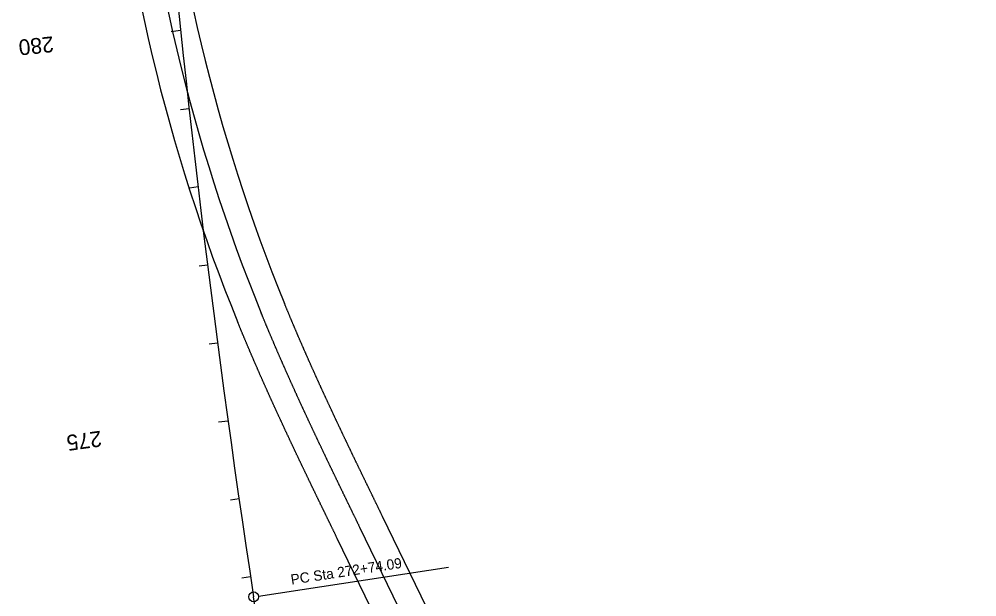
# Model space of a CAD drawing. Extents: x 5180909 to 5237144, y 3695282 to 3720102.
# Drawn here: x 5196668 to 5197885, y 3710731 to 3711465 of the extents above; entities that cross this region are included whole.
import ezdxf

# ---------------------------------------------------------------- set-up
doc = ezdxf.new("R2010")
doc.units = 0
for name, color, linetype in [('Alignment', 7, 'Continuous'), ('brgPreStructureNew', 7, 'Continuous'), ('Default', 7, 'Continuous'), ('DisFieldPoint', 7, 'Continuous'), ('dsnEntrancePaved', 7, 'Continuous'), ('dsnSidewalkShadingRamp', 7, 'Continuous')]:
    doc.layers.add(name, color=color, linetype=linetype)

msp = doc.modelspace()

# ---------------------------------------------------------------- linework, layer by layer
at = {"layer": 'Alignment'}
msp.add_arc((5212287.9, 3713070.6), 15500, 180.86138, 188.68311, dxfattribs=at)
at = {"layer": 'brgPreStructureNew'}
msp.add_open_spline([(5197100.6, 3710818.9), (5197100, 3710820.1), (5197099.4, 3710821.3), (5197098.8, 3710822.6), (5197098.2, 3710823.8), (5197097.6, 3710825), (5197097.1, 3710826.2), (5197096.5, 3710827.4), (5197095.9, 3710828.6), (5197095.3, 3710829.8), (5197094.7, 3710831.1), (5197094.1, 3710832.3), (5197093.5, 3710833.5), (5197092.9, 3710834.7), (5197092.3, 3710835.9), (5197091.7, 3710837.1), (5197091.1, 3710838.4), (5197090.6, 3710839.6), (5197090, 3710840.8), (5197089.4, 3710842), (5197088.8, 3710843.2), (5197088.2, 3710844.4), (5197087.6, 3710845.6), (5197087, 3710846.9), (5197086.4, 3710848.1), (5197085.8, 3710849.3), (5197085.2, 3710850.5), (5197084.6, 3710851.7), (5197084.1, 3710852.9), (5197083.5, 3710854.2), (5197082.9, 3710855.4), (5197082.3, 3710856.6), (5197081.7, 3710857.8), (5197081.1, 3710859), (5197080.5, 3710860.2), (5197079.9, 3710861.5), (5197079.3, 3710862.7), (5197078.8, 3710863.9), (5197078.2, 3710865.1), (5197077.6, 3710866.3), (5197077, 3710867.5), (5197076.4, 3710868.7), (5197075.8, 3710870), (5197075.2, 3710871.2), (5197074.6, 3710872.4), (5197074, 3710873.6), (5197073.5, 3710874.8), (5197072.9, 3710876), (5197072.3, 3710877.3), (5197071.7, 3710878.5), (5197071.1, 3710879.7), (5197070.5, 3710880.9), (5197069.9, 3710882.1), (5197069.3, 3710883.4), (5197068.8, 3710884.6), (5197068.2, 3710885.8), (5197067.6, 3710887), (5197067, 3710888.2), (5197066.4, 3710889.4), (5197065.8, 3710890.7), (5197065.2, 3710891.9), (5197064.7, 3710893.1), (5197064.1, 3710894.3), (5197063.5, 3710895.5), (5197062.9, 3710896.7), (5197062.3, 3710898), (5197061.7, 3710899.2), (5197061.1, 3710900.4), (5197060.6, 3710901.6), (5197060, 3710902.8), (5197059.4, 3710904.1), (5197058.8, 3710905.3), (5197058.2, 3710906.5), (5197057.6, 3710907.7), (5197057.1, 3710908.9), (5197056.5, 3710910.2), (5197055.9, 3710911.4), (5197055.3, 3710912.6), (5197054.7, 3710913.8), (5197054.2, 3710915), (5197053.6, 3710916.3), (5197053, 3710917.5), (5197052.4, 3710918.7), (5197051.8, 3710919.9), (5197051.3, 3710921.1), (5197050.7, 3710922.4), (5197050.1, 3710923.6), (5197049.5, 3710924.8), (5197048.9, 3710926), (5197048.4, 3710927.2), (5197047.8, 3710928.5), (5197047.2, 3710929.7), (5197046.6, 3710930.9), (5197046, 3710932.1), (5197045.5, 3710933.3), (5197044.9, 3710934.6), (5197044.3, 3710935.8), (5197043.7, 3710937), (5197043.2, 3710938.2), (5197042.6, 3710939.5), (5197042, 3710940.7), (5197041.4, 3710941.9), (5197040.9, 3710943.1), (5197040.3, 3710944.4), (5197039.7, 3710945.6), (5197039.1, 3710946.8), (5197038.6, 3710948), (5197038, 3710949.2), (5197037.4, 3710950.5), (5197036.8, 3710951.7), (5197036.3, 3710952.9), (5197035.7, 3710954.1), (5197035.1, 3710955.4), (5197034.6, 3710956.6), (5197034, 3710957.8), (5197033.4, 3710959), (5197032.9, 3710960.3), (5197032.3, 3710961.5), (5197031.7, 3710962.7), (5197031.1, 3710963.9), (5197030.6, 3710965.2), (5197030, 3710966.4), (5197029.4, 3710967.6), (5197028.9, 3710968.9), (5197028.3, 3710970.1), (5197027.7, 3710971.3), (5197027.2, 3710972.5), (5197026.6, 3710973.8), (5197026, 3710975), (5197025.5, 3710976.2), (5197024.9, 3710977.4), (5197024.4, 3710978.7), (5197023.8, 3710979.9), (5197023.2, 3710981.1), (5197022.7, 3710982.4), (5197022.1, 3710983.6), (5197021.5, 3710984.8), (5197021, 3710986), (5197020.4, 3710987.3), (5197019.9, 3710988.5), (5197019.3, 3710989.7), (5197018.7, 3710991), (5197018.2, 3710992.2), (5197017.6, 3710993.4), (5197017.1, 3710994.7), (5197016.5, 3710995.9), (5197016, 3710997.1), (5197015.4, 3710998.4), (5197014.8, 3710999.6), (5197014.3, 3711000.8), (5197013.7, 3711002), (5197013.2, 3711003.3), (5197012.6, 3711004.5), (5197012.1, 3711005.7), (5197011.5, 3711007), (5197011, 3711008.2), (5197010.4, 3711009.4), (5197009.9, 3711010.7), (5197009.3, 3711011.9), (5197008.8, 3711013.1), (5197008.2, 3711014.4), (5197007.7, 3711015.6), (5197007.1, 3711016.8), (5197006.6, 3711018.1), (5197006, 3711019.3), (5197005.5, 3711020.6), (5197004.9, 3711021.8), (5197004.4, 3711023), (5197003.8, 3711024.3), (5197003.3, 3711025.5), (5197002.7, 3711026.7), (5197002.2, 3711028), (5197001.7, 3711029.2), (5197001.1, 3711030.4), (5197000.6, 3711031.7), (5197000, 3711032.9), (5196999.5, 3711034.2), (5196998.9, 3711035.4), (5196998.4, 3711036.6), (5196997.9, 3711037.9), (5196997.3, 3711039.1), (5196996.8, 3711040.4), (5196996.2, 3711041.6), (5196995.7, 3711042.8), (5196995.2, 3711044.1), (5196994.6, 3711045.3), (5196994.1, 3711046.6), (5196993.6, 3711047.8), (5196993, 3711049), (5196992.5, 3711050.3), (5196992, 3711051.5), (5196991.4, 3711052.8), (5196990.9, 3711054), (5196990.4, 3711055.3), (5196989.8, 3711056.5), (5196989.3, 3711057.7), (5196988.8, 3711059), (5196988.3, 3711060.2), (5196987.7, 3711061.5), (5196987.2, 3711062.7), (5196986.7, 3711064), (5196986.2, 3711065.2), (5196985.6, 3711066.4), (5196985.1, 3711067.7), (5196984.6, 3711068.9), (5196984.1, 3711070.2), (5196983.5, 3711071.4), (5196983, 3711072.7), (5196982.5, 3711073.9), (5196982, 3711075.2), (5196981.5, 3711076.4), (5196980.9, 3711077.7), (5196980.4, 3711078.9), (5196979.9, 3711080.2), (5196979.4, 3711081.4), (5196978.9, 3711082.7), (5196978.3, 3711083.9), (5196977.8, 3711085.2), (5196977.3, 3711086.4), (5196976.8, 3711087.7), (5196976.3, 3711088.9), (5196975.8, 3711090.2), (5196975.3, 3711091.4)], degree=3, dxfattribs=at)
msp.add_open_spline([(5197100.6, 3710818.9), (5197100, 3710820.1), (5197099.4, 3710821.3), (5197098.8, 3710822.6), (5197098.2, 3710823.8), (5197097.6, 3710825), (5197097.1, 3710826.2), (5197096.5, 3710827.4), (5197095.9, 3710828.6), (5197095.3, 3710829.8), (5197094.7, 3710831.1), (5197094.1, 3710832.3), (5197093.5, 3710833.5), (5197092.9, 3710834.7), (5197092.3, 3710835.9), (5197091.7, 3710837.1), (5197091.1, 3710838.4), (5197090.6, 3710839.6), (5197090, 3710840.8), (5197089.4, 3710842), (5197088.8, 3710843.2), (5197088.2, 3710844.4), (5197087.6, 3710845.6), (5197087, 3710846.9), (5197086.4, 3710848.1), (5197085.8, 3710849.3), (5197085.2, 3710850.5), (5197084.6, 3710851.7), (5197084.1, 3710852.9), (5197083.5, 3710854.2), (5197082.9, 3710855.4), (5197082.3, 3710856.6), (5197081.7, 3710857.8), (5197081.1, 3710859), (5197080.5, 3710860.2), (5197079.9, 3710861.5), (5197079.3, 3710862.7), (5197078.8, 3710863.9), (5197078.2, 3710865.1), (5197077.6, 3710866.3), (5197077, 3710867.5), (5197076.4, 3710868.7), (5197075.8, 3710870), (5197075.2, 3710871.2), (5197074.6, 3710872.4), (5197074, 3710873.6), (5197073.5, 3710874.8), (5197072.9, 3710876), (5197072.3, 3710877.3), (5197071.7, 3710878.5), (5197071.1, 3710879.7), (5197070.5, 3710880.9), (5197069.9, 3710882.1), (5197069.3, 3710883.4), (5197068.8, 3710884.6), (5197068.2, 3710885.8), (5197067.6, 3710887), (5197067, 3710888.2), (5197066.4, 3710889.4), (5197065.8, 3710890.7), (5197065.2, 3710891.9), (5197064.7, 3710893.1), (5197064.1, 3710894.3), (5197063.5, 3710895.5), (5197062.9, 3710896.7), (5197062.3, 3710898), (5197061.7, 3710899.2), (5197061.1, 3710900.4), (5197060.6, 3710901.6), (5197060, 3710902.8), (5197059.4, 3710904.1), (5197058.8, 3710905.3), (5197058.2, 3710906.5), (5197057.6, 3710907.7), (5197057.1, 3710908.9), (5197056.5, 3710910.2), (5197055.9, 3710911.4), (5197055.3, 3710912.6), (5197054.7, 3710913.8), (5197054.2, 3710915), (5197053.6, 3710916.3), (5197053, 3710917.5), (5197052.4, 3710918.7), (5197051.8, 3710919.9), (5197051.3, 3710921.1), (5197050.7, 3710922.4), (5197050.1, 3710923.6), (5197049.5, 3710924.8), (5197048.9, 3710926), (5197048.4, 3710927.2), (5197047.8, 3710928.5), (5197047.2, 3710929.7), (5197046.6, 3710930.9), (5197046, 3710932.1), (5197045.5, 3710933.3), (5197044.9, 3710934.6), (5197044.3, 3710935.8), (5197043.7, 3710937), (5197043.2, 3710938.2), (5197042.6, 3710939.5), (5197042, 3710940.7), (5197041.4, 3710941.9), (5197040.9, 3710943.1), (5197040.3, 3710944.4), (5197039.7, 3710945.6), (5197039.1, 3710946.8), (5197038.6, 3710948), (5197038, 3710949.2), (5197037.4, 3710950.5), (5197036.8, 3710951.7), (5197036.3, 3710952.9), (5197035.7, 3710954.1), (5197035.1, 3710955.4), (5197034.6, 3710956.6), (5197034, 3710957.8), (5197033.4, 3710959), (5197032.9, 3710960.3), (5197032.3, 3710961.5), (5197031.7, 3710962.7), (5197031.1, 3710963.9), (5197030.6, 3710965.2), (5197030, 3710966.4), (5197029.4, 3710967.6), (5197028.9, 3710968.9), (5197028.3, 3710970.1), (5197027.7, 3710971.3), (5197027.2, 3710972.5), (5197026.6, 3710973.8), (5197026, 3710975), (5197025.5, 3710976.2), (5197024.9, 3710977.4), (5197024.4, 3710978.7), (5197023.8, 3710979.9), (5197023.2, 3710981.1), (5197022.7, 3710982.4), (5197022.1, 3710983.6), (5197021.5, 3710984.8), (5197021, 3710986), (5197020.4, 3710987.3), (5197019.9, 3710988.5), (5197019.3, 3710989.7), (5197018.7, 3710991), (5197018.2, 3710992.2), (5197017.6, 3710993.4), (5197017.1, 3710994.7), (5197016.5, 3710995.9), (5197016, 3710997.1), (5197015.4, 3710998.4), (5197014.8, 3710999.6), (5197014.3, 3711000.8), (5197013.7, 3711002), (5197013.2, 3711003.3), (5197012.6, 3711004.5), (5197012.1, 3711005.7), (5197011.5, 3711007), (5197011, 3711008.2), (5197010.4, 3711009.4), (5197009.9, 3711010.7), (5197009.3, 3711011.9), (5197008.8, 3711013.1), (5197008.2, 3711014.4), (5197007.7, 3711015.6), (5197007.1, 3711016.8), (5197006.6, 3711018.1), (5197006, 3711019.3), (5197005.5, 3711020.6), (5197004.9, 3711021.8), (5197004.4, 3711023), (5197003.8, 3711024.3), (5197003.3, 3711025.5), (5197002.7, 3711026.7), (5197002.2, 3711028), (5197001.7, 3711029.2), (5197001.1, 3711030.4), (5197000.6, 3711031.7), (5197000, 3711032.9), (5196999.5, 3711034.2), (5196998.9, 3711035.4), (5196998.4, 3711036.6), (5196997.9, 3711037.9), (5196997.3, 3711039.1), (5196996.8, 3711040.4), (5196996.2, 3711041.6), (5196995.7, 3711042.8), (5196995.2, 3711044.1), (5196994.6, 3711045.3), (5196994.1, 3711046.6), (5196993.6, 3711047.8), (5196993, 3711049), (5196992.5, 3711050.3), (5196992, 3711051.5), (5196991.4, 3711052.8), (5196990.9, 3711054), (5196990.4, 3711055.3), (5196989.8, 3711056.5), (5196989.3, 3711057.7), (5196988.8, 3711059), (5196988.3, 3711060.2), (5196987.7, 3711061.5), (5196987.2, 3711062.7), (5196986.7, 3711064), (5196986.2, 3711065.2), (5196985.6, 3711066.4), (5196985.1, 3711067.7), (5196984.6, 3711068.9), (5196984.1, 3711070.2), (5196983.5, 3711071.4), (5196983, 3711072.7), (5196982.5, 3711073.9), (5196982, 3711075.2), (5196981.5, 3711076.4), (5196980.9, 3711077.7), (5196980.4, 3711078.9), (5196979.9, 3711080.2), (5196979.4, 3711081.4), (5196978.9, 3711082.7), (5196978.3, 3711083.9), (5196977.8, 3711085.2), (5196977.3, 3711086.4), (5196976.8, 3711087.7), (5196976.3, 3711088.9), (5196975.8, 3711090.2), (5196975.3, 3711091.4)], degree=3, dxfattribs=at)
at = {"layer": 'Default'}
msp.add_line((5197884.8, 3704711.8), (5196965.6, 3710730.6), dxfattribs=at)
msp.add_arc((5212287.9, 3713070.6), 15500, 180.86138, 188.68311, dxfattribs=at)
at = {"layer": 'DisFieldPoint'}
for p, q in [((5196945.7, 3711079.3), (5196945.6, 3711079.3)), ((5196945.7, 3711079.3), (5196945.7, 3711079.3)), ((5197264.6, 3710555.1), (5197129.4, 3710832.9)), ((5197235.8, 3710541.1), (5197100.6, 3710818.9)), ((5197207, 3710527.1), (5197071.8, 3710804.9))]:
    msp.add_line(p, q, dxfattribs=at)
for radius, start, end in [(2323.8, 184.6079, 202.1984), (2291.8, 184.6079, 202.1984), (2259.8, 184.6083, 202.198)]:
    msp.add_arc((5199097.2, 3711957.3), radius, start, end, dxfattribs=at)
for points in [[(5197129.4, 3710832.9), (5197128.8, 3710834.1), (5197128.2, 3710835.3), (5197127.6, 3710836.6), (5197127, 3710837.8), (5197126.4, 3710839), (5197125.8, 3710840.2), (5197125.2, 3710841.4), (5197124.6, 3710842.6), (5197124.1, 3710843.8), (5197123.5, 3710845.1), (5197122.9, 3710846.3), (5197122.3, 3710847.5), (5197121.7, 3710848.7), (5197121.1, 3710849.9), (5197120.5, 3710851.1), (5197119.9, 3710852.3), (5197119.3, 3710853.6), (5197118.7, 3710854.8), (5197118.2, 3710856), (5197117.6, 3710857.2), (5197117, 3710858.4), (5197116.4, 3710859.6), (5197115.8, 3710860.8), (5197115.2, 3710862.1), (5197114.6, 3710863.3), (5197114, 3710864.5), (5197113.4, 3710865.7), (5197112.8, 3710866.9), (5197112.3, 3710868.1), (5197111.7, 3710869.3), (5197111.1, 3710870.6), (5197110.5, 3710871.8), (5197109.9, 3710873), (5197109.3, 3710874.2), (5197108.7, 3710875.4), (5197108.1, 3710876.6), (5197107.6, 3710877.8), (5197107, 3710879), (5197106.4, 3710880.3), (5197105.8, 3710881.5), (5197105.2, 3710882.7), (5197104.6, 3710883.9), (5197104, 3710885.1), (5197103.4, 3710886.3), (5197102.9, 3710887.5), (5197102.3, 3710888.8), (5197101.7, 3710890), (5197101.1, 3710891.2), (5197100.5, 3710892.4), (5197099.9, 3710893.6), (5197099.3, 3710894.8), (5197098.8, 3710896), (5197098.2, 3710897.2), (5197097.6, 3710898.5), (5197097, 3710899.7), (5197096.4, 3710900.9), (5197095.8, 3710902.1), (5197095.2, 3710903.3), (5197094.7, 3710904.5), (5197094.1, 3710905.7), (5197093.5, 3710907), (5197092.9, 3710908.2), (5197092.3, 3710909.4), (5197091.7, 3710910.6), (5197091.2, 3710911.8), (5197090.6, 3710913), (5197090, 3710914.2), (5197089.4, 3710915.4), (5197088.8, 3710916.7), (5197088.3, 3710917.9), (5197087.7, 3710919.1), (5197087.1, 3710920.3), (5197086.5, 3710921.5), (5197085.9, 3710922.7), (5197085.4, 3710923.9), (5197084.8, 3710925.2), (5197084.2, 3710926.4), (5197083.6, 3710927.6), (5197083, 3710928.8), (5197082.5, 3710930), (5197081.9, 3710931.2), (5197081.3, 3710932.4), (5197080.7, 3710933.7), (5197080.2, 3710934.9), (5197079.6, 3710936.1), (5197079, 3710937.3), (5197078.4, 3710938.5), (5197077.9, 3710939.7), (5197077.3, 3710940.9), (5197076.7, 3710942.2), (5197076.1, 3710943.4), (5197075.6, 3710944.6), (5197075, 3710945.8), (5197074.4, 3710947), (5197073.8, 3710948.2), (5197073.3, 3710949.4), (5197072.7, 3710950.7), (5197072.1, 3710951.9), (5197071.5, 3710953.1), (5197071, 3710954.3), (5197070.4, 3710955.5), (5197069.8, 3710956.7), (5197069.3, 3710957.9), (5197068.7, 3710959.2), (5197068.1, 3710960.4), (5197067.5, 3710961.6), (5197067, 3710962.8), (5197066.4, 3710964), (5197065.8, 3710965.2), (5197065.3, 3710966.5), (5197064.7, 3710967.7), (5197064.1, 3710968.9), (5197063.6, 3710970.1), (5197063, 3710971.3), (5197062.4, 3710972.5), (5197061.9, 3710973.8), (5197061.3, 3710975), (5197060.7, 3710976.2), (5197060.2, 3710977.4), (5197059.6, 3710978.6), (5197059.1, 3710979.8), (5197058.5, 3710981.1), (5197057.9, 3710982.3), (5197057.4, 3710983.5), (5197056.8, 3710984.7), (5197056.2, 3710985.9), (5197055.7, 3710987.1), (5197055.1, 3710988.4), (5197054.6, 3710989.6), (5197054, 3710990.8), (5197053.4, 3710992), (5197052.9, 3710993.2), (5197052.3, 3710994.5), (5197051.8, 3710995.7), (5197051.2, 3710996.9), (5197050.7, 3710998.1), (5197050.1, 3710999.3), (5197049.5, 3711000.5), (5197049, 3711001.8), (5197048.4, 3711003), (5197047.9, 3711004.2), (5197047.3, 3711005.4), (5197046.8, 3711006.6), (5197046.2, 3711007.9), (5197045.7, 3711009.1), (5197045.1, 3711010.3), (5197044.6, 3711011.5), (5197044, 3711012.7), (5197043.5, 3711014), (5197042.9, 3711015.2), (5197042.4, 3711016.4), (5197041.8, 3711017.6), (5197041.3, 3711018.8), (5197040.7, 3711020.1), (5197040.2, 3711021.3), (5197039.6, 3711022.5), (5197039.1, 3711023.7), (5197038.5, 3711025), (5197038, 3711026.2), (5197037.4, 3711027.4), (5197036.9, 3711028.6), (5197036.4, 3711029.8), (5197035.8, 3711031.1), (5197035.3, 3711032.3), (5197034.7, 3711033.5), (5197034.2, 3711034.7), (5197033.6, 3711036), (5197033.1, 3711037.2), (5197032.6, 3711038.4), (5197032, 3711039.6), (5197031.5, 3711040.8), (5197031, 3711042.1), (5197030.4, 3711043.3), (5197029.9, 3711044.5), (5197029.3, 3711045.7), (5197028.8, 3711047), (5197028.3, 3711048.2), (5197027.7, 3711049.4), (5197027.2, 3711050.6), (5197026.7, 3711051.9), (5197026.1, 3711053.1), (5197025.6, 3711054.3), (5197025.1, 3711055.5), (5197024.5, 3711056.8), (5197024, 3711058), (5197023.5, 3711059.2), (5197023, 3711060.5), (5197022.4, 3711061.7), (5197021.9, 3711062.9), (5197021.4, 3711064.1), (5197020.9, 3711065.4), (5197020.3, 3711066.6), (5197019.8, 3711067.8), (5197019.3, 3711069), (5197018.8, 3711070.3), (5197018.2, 3711071.5), (5197017.7, 3711072.7), (5197017.2, 3711074), (5197016.7, 3711075.2), (5197016.2, 3711076.4), (5197015.6, 3711077.6), (5197015.1, 3711078.9), (5197014.6, 3711080.1), (5197014.1, 3711081.3), (5197013.6, 3711082.6), (5197013.1, 3711083.8), (5197012.5, 3711085), (5197012, 3711086.3), (5197011.5, 3711087.5), (5197011, 3711088.7), (5197010.5, 3711089.9), (5197010, 3711091.2), (5197009.5, 3711092.4), (5197009, 3711093.6), (5197008.4, 3711094.9), (5197007.9, 3711096.1), (5197007.4, 3711097.4), (5197006.9, 3711098.6), (5197006.4, 3711099.8), (5197005.9, 3711101), (5197005.4, 3711102.3), (5197004.9, 3711103.5)], [(5197071.8, 3710804.9), (5197071.2, 3710806.1), (5197070.6, 3710807.3), (5197070.1, 3710808.6), (5197069.5, 3710809.8), (5197068.9, 3710811), (5197068.3, 3710812.2), (5197067.7, 3710813.4), (5197067.1, 3710814.6), (5197066.5, 3710815.8), (5197065.9, 3710817.1), (5197065.3, 3710818.3), (5197064.7, 3710819.5), (5197064.1, 3710820.7), (5197063.5, 3710821.9), (5197063, 3710823.1), (5197062.4, 3710824.4), (5197061.8, 3710825.6), (5197061.2, 3710826.8), (5197060.6, 3710828), (5197060, 3710829.2), (5197059.4, 3710830.4), (5197058.8, 3710831.7), (5197058.2, 3710832.9), (5197057.6, 3710834.1), (5197057, 3710835.3), (5197056.5, 3710836.5), (5197055.9, 3710837.7), (5197055.3, 3710839), (5197054.7, 3710840.2), (5197054.1, 3710841.4), (5197053.5, 3710842.6), (5197052.9, 3710843.8), (5197052.3, 3710845.1), (5197051.7, 3710846.3), (5197051.1, 3710847.5), (5197050.5, 3710848.7), (5197050, 3710849.9), (5197049.4, 3710851.2), (5197048.8, 3710852.4), (5197048.2, 3710853.6), (5197047.6, 3710854.8), (5197047, 3710856), (5197046.4, 3710857.3), (5197045.8, 3710858.5), (5197045.2, 3710859.7), (5197044.6, 3710860.9), (5197044.1, 3710862.1), (5197043.5, 3710863.4), (5197042.9, 3710864.6), (5197042.3, 3710865.8), (5197041.7, 3710867), (5197041.1, 3710868.2), (5197040.5, 3710869.5), (5197039.9, 3710870.7), (5197039.3, 3710871.9), (5197038.8, 3710873.1), (5197038.2, 3710874.3), (5197037.6, 3710875.6), (5197037, 3710876.8), (5197036.4, 3710878), (5197035.8, 3710879.2), (5197035.2, 3710880.5), (5197034.6, 3710881.7), (5197034, 3710882.9), (5197033.5, 3710884.1), (5197032.9, 3710885.3), (5197032.3, 3710886.6), (5197031.7, 3710887.8), (5197031.1, 3710889), (5197030.5, 3710890.2), (5197029.9, 3710891.5), (5197029.4, 3710892.7), (5197028.8, 3710893.9), (5197028.2, 3710895.1), (5197027.6, 3710896.4), (5197027, 3710897.6), (5197026.4, 3710898.8), (5197025.8, 3710900), (5197025.3, 3710901.3), (5197024.7, 3710902.5), (5197024.1, 3710903.7), (5197023.5, 3710904.9), (5197022.9, 3710906.2), (5197022.3, 3710907.4), (5197021.8, 3710908.6), (5197021.2, 3710909.9), (5197020.6, 3710911.1), (5197020, 3710912.3), (5197019.4, 3710913.5), (5197018.9, 3710914.8), (5197018.3, 3710916), (5197017.7, 3710917.2), (5197017.1, 3710918.5), (5197016.5, 3710919.7), (5197016, 3710920.9), (5197015.4, 3710922.1), (5197014.8, 3710923.4), (5197014.2, 3710924.6), (5197013.6, 3710925.8), (5197013.1, 3710927.1), (5197012.5, 3710928.3), (5197011.9, 3710929.5), (5197011.3, 3710930.8), (5197010.7, 3710932), (5197010.2, 3710933.2), (5197009.6, 3710934.5), (5197009, 3710935.7), (5197008.4, 3710936.9), (5197007.9, 3710938.1), (5197007.3, 3710939.4), (5197006.7, 3710940.6), (5197006.1, 3710941.8), (5197005.6, 3710943.1), (5197005, 3710944.3), (5197004.4, 3710945.5), (5197003.8, 3710946.8), (5197003.3, 3710948), (5197002.7, 3710949.3), (5197002.1, 3710950.5), (5197001.5, 3710951.7), (5197001, 3710953), (5197000.4, 3710954.2), (5196999.8, 3710955.4), (5196999.3, 3710956.7), (5196998.7, 3710957.9), (5196998.1, 3710959.1), (5196997.5, 3710960.4), (5196997, 3710961.6), (5196996.4, 3710962.9), (5196995.8, 3710964.1), (5196995.3, 3710965.3), (5196994.7, 3710966.6), (5196994.1, 3710967.8), (5196993.6, 3710969), (5196993, 3710970.3), (5196992.4, 3710971.5), (5196991.9, 3710972.8), (5196991.3, 3710974), (5196990.7, 3710975.2), (5196990.2, 3710976.5), (5196989.6, 3710977.7), (5196989, 3710979), (5196988.5, 3710980.2), (5196987.9, 3710981.5), (5196987.4, 3710982.7), (5196986.8, 3710983.9), (5196986.2, 3710985.2), (5196985.7, 3710986.4), (5196985.1, 3710987.7), (5196984.6, 3710988.9), (5196984, 3710990.2), (5196983.4, 3710991.4), (5196982.9, 3710992.6), (5196982.3, 3710993.9), (5196981.8, 3710995.1), (5196981.2, 3710996.4), (5196980.6, 3710997.6), (5196980.1, 3710998.9), (5196979.5, 3711000.1), (5196979, 3711001.4), (5196978.4, 3711002.6), (5196977.9, 3711003.9), (5196977.3, 3711005.1), (5196976.8, 3711006.4), (5196976.2, 3711007.6), (5196975.7, 3711008.9), (5196975.1, 3711010.1), (5196974.5, 3711011.3), (5196974, 3711012.6), (5196973.4, 3711013.8), (5196972.9, 3711015.1), (5196972.3, 3711016.4), (5196971.8, 3711017.6), (5196971.3, 3711018.9), (5196970.7, 3711020.1), (5196970.2, 3711021.4), (5196969.6, 3711022.6), (5196969.1, 3711023.9), (5196968.5, 3711025.1), (5196968, 3711026.4), (5196967.4, 3711027.6), (5196966.9, 3711028.9), (5196966.3, 3711030.1), (5196965.8, 3711031.4), (5196965.3, 3711032.6), (5196964.7, 3711033.9), (5196964.2, 3711035.1), (5196963.6, 3711036.4), (5196963.1, 3711037.7), (5196962.6, 3711038.9), (5196962, 3711040.2), (5196961.5, 3711041.4), (5196960.9, 3711042.7), (5196960.4, 3711043.9), (5196959.9, 3711045.2), (5196959.3, 3711046.5), (5196958.8, 3711047.7), (5196958.3, 3711049), (5196957.7, 3711050.2), (5196957.2, 3711051.5), (5196956.7, 3711052.8), (5196956.1, 3711054), (5196955.6, 3711055.3), (5196955.1, 3711056.5), (5196954.5, 3711057.8), (5196954, 3711059.1), (5196953.5, 3711060.3), (5196953, 3711061.6), (5196952.4, 3711062.9), (5196951.9, 3711064.1), (5196951.4, 3711065.4), (5196950.9, 3711066.7), (5196950.3, 3711067.9), (5196949.8, 3711069.2), (5196949.3, 3711070.5), (5196948.8, 3711071.7), (5196948.2, 3711073), (5196947.7, 3711074.2), (5196947.2, 3711075.5), (5196946.7, 3711076.8), (5196946.2, 3711078), (5196945.7, 3711079.3)]]:
    msp.add_open_spline(points, degree=3, dxfattribs=at)
at = {"layer": 'dsnEntrancePaved'}
msp.add_arc((5212287.9, 3713070.6), 15500, 180.86138, 188.68311, dxfattribs=at)
at = {"layer": 'dsnSidewalkShadingRamp'}
for p, q in [((5196872.8, 3711450.5), (5196860.6, 3711449.2)), ((5196883.6, 3711351), (5196872.7, 3711349.8)), ((5196895, 3711251.7), (5196884.1, 3711250.4)), ((5196907.1, 3711152.4), (5196896.2, 3711151.1)), ((5196919.8, 3711053.2), (5196908.9, 3711051.8)), ((5196933.1, 3710954.1), (5196921, 3710952.5)), ((5196947.1, 3710855.1), (5196936.2, 3710853.5)), ((5196971.8, 3710731.5), (5197213.1, 3710768.4)), ((5196961.7, 3710756.2), (5196950.8, 3710754.5))]:
    msp.add_line(p, q, dxfattribs=at)
msp.add_circle((5196965.6, 3710730.6), 6.25, dxfattribs=at)

# ---------------------------------------------------------------- texts
for s, height, rotation, p in [('280', 20, 185.9998, (5196710.4, 3711443.4)), ('275', 20, 187.848, (5196771, 3710941.9)), ('PC Sta 272+74.09', 13, 8.6831, (5197013.8, 3710746))]:
    msp.add_text(s, height=height, rotation=rotation, dxfattribs=at).set_placement(p)

doc.saveas('drawing.dxf')
